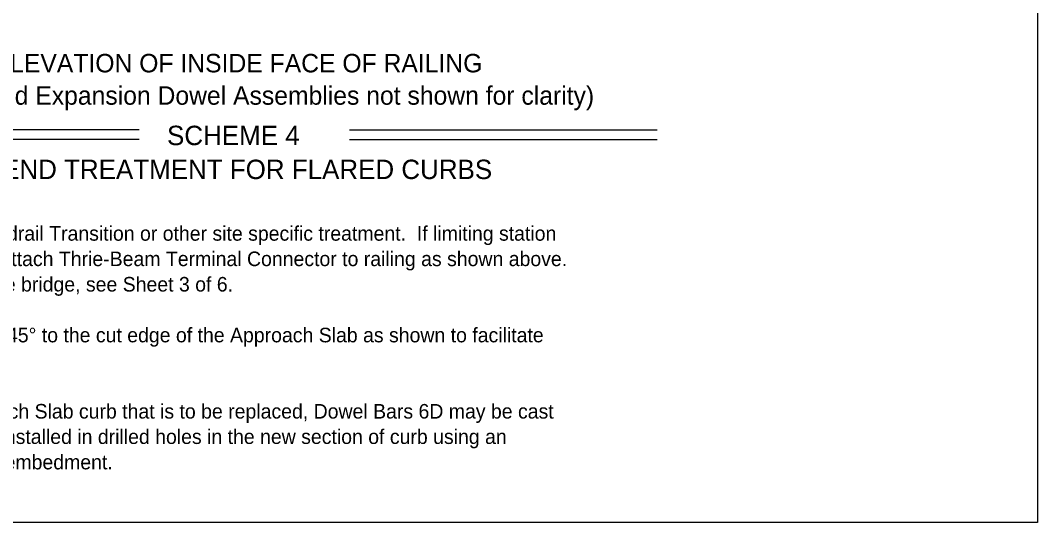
# Model space of a CAD drawing. Extents: x 1.5 to 68.7, y 0 to 31.1.
# Drawn here: x 28.44 to 42.53, y 1.78 to 8.74 of the extents above; entities that cross this region are included whole.
import ezdxf

# ---------------------------------------------------------------- set-up
doc = ezdxf.new("R2010")
doc.units = 0
doc.layers.add('ActivePts-ConstElements', color=7, linetype='Continuous')
doc.layers.add('Dimension', color=7, linetype='Continuous')

msp = doc.modelspace()

# ---------------------------------------------------------------- linework, layer by layer
at = {"layer": 'ActivePts-ConstElements'}
msp.add_lwpolyline([(1.467, 28.183), (42.533, 28.183), (42.533, 1.783), (1.467, 1.783)], close=True, dxfattribs=at)
at = {"layer": 'Dimension'}
for p, q in [((30.085, 7.224), (25.826, 7.224)), ((33, 7.224), (37.259, 7.224)), ((30.085, 7.091), (25.826, 7.091)), ((33, 7.091), (37.259, 7.091))]:
    msp.add_line(p, q, dxfattribs=at)

# ---------------------------------------------------------------- texts
for s, height, p in [('PARTIAL ELEVATION OF INSIDE FACE OF RAILING', 0.256, (26.546, 8.021)), ('(Existing Wing Post, Railing Reinforcing and Expansion Dowel Assemblies not shown for clarity)', 0.256, (21.852, 7.573)), ('SCHEME 4', 0.2688, (30.47, 7.013)), ('RAILING END TREATMENT FOR FLARED CURBS', 0.2688, (26.647, 6.543)), ('1. See Roadway Plans for limiting station of Roadway Guardrail Transition or other site specific treatment.  If limiting station ', 0.2016, (21.18, 5.689)), ('   of Roadway Guardrail Transition is along the Wing Wall, attach Thrie-Beam Terminal Connector to railing as shown above.  ', 0.2016, (21.18, 5.337)), ('   If limiting station of Roadway Guardrail Transition is on the bridge, see Sheet 3 of 6.', 0.2016, (21.18, 4.985)), ('2. Dowel Bars 4N may be installed on a maximum angle of 45° to the cut edge of the Approach Slab as shown to facilitate ', 0.2016, (21.18, 4.281)), ("3. At the Contractor's option, along the length of the Approach Slab curb that is to be replaced, Dowel Bars 6D may be cast ", 0.2016, (21.18, 3.225)), ('   in with the new section of curb as shown or they may be installed in drilled holes in the new section of curb using an ', 0.2016, (21.18, 2.873)), ('   Adhesive Bonding Material System with a 1\'-0" minimum embedment. ', 0.2016, (21.18, 2.521))]:
    msp.add_text(s, height=height, dxfattribs=at).set_placement(p)

doc.saveas('drawing.dxf')
